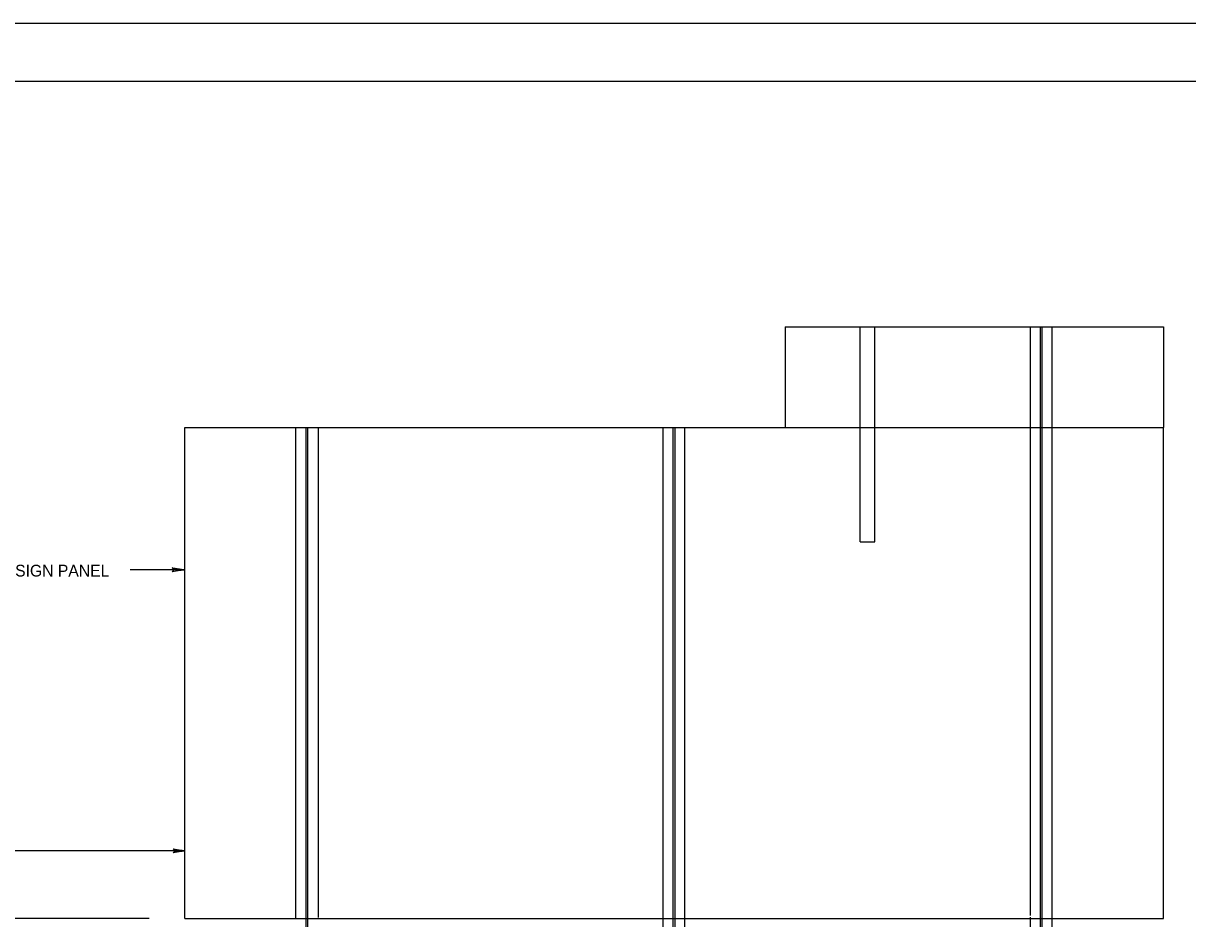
# Model space of a CAD drawing. Extents: x 637580 to 641008, y 294594 to 295782.
# Drawn here: x 637867.6 to 638169.4, y 295549.6 to 295781.6 of the extents above; entities that cross this region are included whole.
import ezdxf

# ---------------------------------------------------------------- set-up
doc = ezdxf.new("R2010")
doc.units = 0
for name, color, linetype in [('1', 7, 'Continuous'), ('2', 7, 'Continuous'), ('3', 7, 'Continuous'), ('PLT-BNDY', 7, 'Continuous')]:
    doc.layers.add(name, color=color, linetype=linetype)

# ---------------------------------------------------------------- blocks, each defined once
blk = doc.blocks.new('RARROW')
at = {"layer": '3'}
blk.add_lwpolyline([(-2.2695, 0.285), (-2.184875, 0.12075), (0, 0), (-2.2695, 0.285), (-2.38575, 0.384625), (0, 0), (-2.183125, -0.108), (-2.262875, -0.2705), (0, 0), (-2.38575, -0.379125), (-2.262875, -0.2705)], dxfattribs=at)

msp = doc.modelspace()

# ---------------------------------------------------------------- linework, layer by layer
at = {"layer": '1'}
msp.add_line((637620.31, 295766.63), (638406.31, 295766.63), dxfattribs=at)
at = {"layer": '2'}
for p, q in [((638065.06, 295703), (638065.06, 295676.88)), ((638065.06, 295703), (638163.19, 295703)), ((638084.56, 295647.25), (638084.56, 295703)), ((638088.31, 295647.25), (638088.31, 295703)), ((638128.69, 295550.38), (638128.69, 295703)), ((638131.31, 295500.38), (638131.31, 295703)), ((638131.69, 295500.5), (638131.69, 295703)), ((638134.31, 295549.88), (638134.31, 295703)), ((638163.19, 295703), (638163.19, 295676.88)), ((637909.44, 295549.63), (637909.44, 295676.88)), ((637909.44, 295676.88), (638163.19, 295676.88)), ((637938.19, 295549.5), (637938.19, 295676.88)), ((637940.94, 295461.88), (637940.94, 295676.88)), ((637941.31, 295461.88), (637941.31, 295676.88)), ((637944.06, 295549.88), (637944.06, 295676.88)), ((638033.44, 295549.88), (638033.44, 295676.88)), ((638036.06, 295453.5), (638036.06, 295676.88)), ((638036.56, 295453.5), (638036.56, 295676.88)), ((638039.06, 295549.88), (638039.06, 295676.88)), ((638163.19, 295549.63), (638163.19, 295676.88)), ((638084.56, 295647.25), (638088.31, 295647.25)), ((637909.19, 295640), (637895.31, 295640)), ((637909.44, 295567.13), (637719.19, 295567.13)), ((637900.19, 295549.63), (637854.94, 295549.63)), ((637909.44, 295549.63), (638163.19, 295549.63)), ((638033.44, 295461.13), (638033.44, 295549.88)), ((638039.06, 295461.13), (638039.06, 295549.88)), ((638128.69, 295434.63), (638128.69, 295550)), ((638134.31, 295434.63), (638134.31, 295549.88))]:
    msp.add_line(p, q, dxfattribs=at)
at = {"layer": 'PLT-BNDY'}
msp.add_lwpolyline([(637580.31, 295781.63), (638421.31, 295781.63), (638421.31, 295187.63), (637580.31, 295187.63)], close=True, dxfattribs=at)

# ---------------------------------------------------------------- block references
at = {"layer": '2', "xscale": 1.2574347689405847, "yscale": 1.3092961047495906}
for p in [(637909.19, 295640), (637909.44, 295567.13)]:
    msp.add_blockref('RARROW', p, dxfattribs=at)

# ---------------------------------------------------------------- texts
at = {"layer": '1'}
msp.add_text('SIGN PANEL', height=3.043, dxfattribs=at).set_placement((637865.44, 295638.25))

doc.saveas('drawing.dxf')
